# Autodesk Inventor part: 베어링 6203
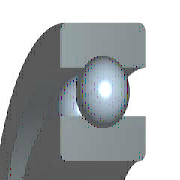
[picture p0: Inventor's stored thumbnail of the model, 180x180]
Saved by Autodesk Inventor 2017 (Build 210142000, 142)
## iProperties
IsCustomPart: 1
Created: 2015-09
Part Number: 베어링 6203
Material: 강철, 연강
Description: 깊은 그루브 볼 베어링
Document SubType Name: Modeling
Standard: KS B 2023
Standards Organization: KS
Language: ko-KR
Size Designation: 6203 - 17 x 40 x 12
Categories: <MemberInstance><Categories><Category DisplayName="샤프트 부품" InternalName="7f7aeb1f-a693-4053-b835-cee3144e0d98" Mnemonic="SHFT"><Category DisplayName="베어링" Inter
Density: 7.86 g/cm^3
Mass: 64.9809 g
Surface Area: 64.3582 cm^2
Volume: 8.26729 cm^3
Appearance: 노란색
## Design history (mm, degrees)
sketch "스케치" dims "d0" = 5.98 (= -0.26 x WD + 0.26 x BD)
  geometry: L1 (3.01, 14.25)-(8.99, 14.25); L2 (6, 14.25)-(6, 11.26); L3 (6, 14.25)-(6, 17.24); L4 (3.778, 12.249)-(0, 12.249); L5 (0, 8.5)-(12, 8.5); L6 (3.778, 16.251)-(0, 16.251); L7 (0, 20)-(12, 20); L8 (12, 8.5)-(12, 12.249); L9 (8.222, 12.249)-(12, 12.249); L10 (8.222, 16.251)-(12, 16.251); L11 (12, 20)-(12, 16.251); L12 (-1.4, 0)-(8.4, 0) reference; L13 (0, -0.3)-(0, 5.3) reference
  constraints: 22 end point, 4 point on line, 2 collinear, 2 perpendicular, 2 symmetric about line, 1 midpoint, 1 parallel, 14 other
  dimensions: "d9" = 17 diameter of L5 L12 (= WD); "d11" = 40 diameter of L7 L12 (= BD); "d12" = 12 distance between parallel lines of L8 L13 (= KB); "d13" = 24.498 diameter of L9 L12 (= 0.326 x BD + 0.674 x WD)
revolve "본체" stored, may be unused: angle "d6" = 90 deg
revolve "볼" stored, may be unused: angle "d7" = 90 deg
pattern_circular "IDS_ARRAYBALL[SIMPL:T]" dims angle "d3" = 360 deg
body "Solid1"
fillet "모깎기1" dims "d1" = 0.6 (= KRS)
other parameters: "WD" = 17 [user parameter; used in 5 equation terms], "BD" = 40 [user parameter; used in 5 equation terms], "KB" = 12 [user parameter; used in 1 equation term], "KRS" = 0.6 [user parameter; used in 1 equation term], "d4" = 0, "d5" = 0, "d8" = 0, "d14" = 0, "d15" = 0, "BBA" = 0 [user parameter], "BC0" = 4750000 [user parameter], "BC" = 9560000 [user parameter], "WR" = 8.5 (= 0.5 x WD) [user parameter]
